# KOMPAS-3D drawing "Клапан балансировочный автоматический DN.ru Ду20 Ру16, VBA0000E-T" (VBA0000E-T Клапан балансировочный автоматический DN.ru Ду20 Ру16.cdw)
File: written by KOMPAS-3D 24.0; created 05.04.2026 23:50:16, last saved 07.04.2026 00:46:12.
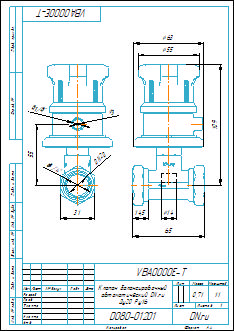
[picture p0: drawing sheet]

Document properties: Автор: tyuri; Форматы листов документа: A4; Полное имя файла: VBA0000E-T Клапан балансировочный автоматический DN.ru Ду20 Ру16.m3d; Масса: 0.706; Наименование: Клапан балансировочный автоматический DN.ru Ду20 Ру16; Количество листов документа: 1; Примечание: D080-01201

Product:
- Body: Тело 5  | qty 1
    Масса: 1.11353
- Part/product: Клапан балансировочный автоматический DN.ru Ду20 Ру16  | designation VBA0000E-T
    Масса: 0.706
    Раздел спецификации: Прочие изделия
    Примечание: D080-01201

Views: Вид 1, Сзади, Проекционный вид 2
Referenced files in D:\Аутсорс\Клапан балансировочный автоматический DN.ru VBA0000E-T Ду15 Ру16\DN15\: Клапан балансировочный автоматический DN.ru Ду15 Ру16.m3d, VBA0000E-T - Клапан балансировочный автоматический DN.ru Ду15 Ру16.cdw
Referenced files in D:\Аутсорс\VBA0000E-T Клапан балансировочный автоматический DN.ru\DN20\: VBA0000E-T Клапан балансировочный автоматический DN.ru Ду20 Ру16.m3d
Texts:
  VBA0000E-T
  Клапан балансировочный
  автоматический DN.ru
  Ду20 Ру16
  Клапан балансировочный автоматический DN.ru Ду20 Ру16
  VBA0000E-T Клапан балансировочный автоматический DN.ru Ду20 Ру16
Dimensions and other numbers on the sheet: 0; 3; 2; 4; 31; 55; 20; 65; 109; 63; 14,5; 14; 1:1; 1; 0,71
